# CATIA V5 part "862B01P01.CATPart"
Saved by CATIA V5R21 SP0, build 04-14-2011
Part number: 862B01P01
Bounding box of the stored display mesh (mm): x -25.75 to 25.25, y -25.549 to 25.54, z -6.5 to 6.5
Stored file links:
  C:\Users\ALI OZGUN\Desktop\alhan\862B01P01.CATPart
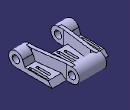
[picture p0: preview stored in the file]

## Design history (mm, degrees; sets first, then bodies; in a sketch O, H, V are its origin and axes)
Body1 (main body)
  Sketch1 on yz-plane, origin (0, 0, 0), H (0, 1, 0), V (0, 0, 1)
    construction line L1 (-19.05, 0) -> (19.05, 0)
    point P1 (-19.05, 0)
    point P2 (19.05, 0)
    line L2 (-19.05, 6.5) -> (19.05, 6.5)
    line L3 (19.05, -6.5) -> (-19.05, -6.5)
    arc A1 centre (19.05, 0) radius 6.5 from (19.05, 6.5) to (19.05, -6.5) cw
    arc A2 centre (-19.05, 0) radius 6.5 from (-19.05, -6.5) to (-19.05, 6.5) cw
    circle A3 centre (19.05, 0) radius 3.25
    circle A4 centre (-19.05, 0) radius 3.25
    distance L1 L2 = 6.5
    length L1 = 38.1
    distance P2 V = 19.05
    radius A3 = 3.25
    radius A4 = 3.25
    coincidence: P1 H
    horizontal: L1 H
    tangency: A1 L2, A2 L2, A1 L3, A2 L3
  Pad1: profile Sketch1, direction (1, 0, 0), length 76.5, mirrored extent
  Sketch2 on face of Pad1 from Sketch1.L2, origin (0, 0, 6.5), H (1, 0, 0), V (0, 1, 0)
    line L1 (38, -14) -> (64, -14)
    line L2 (64, -14) -> (64, -36.0786)
    line L3 (64, -36.0786) -> (38, -36.0786)
    line L4 (38, -36.0786) -> (38, -14)
    line L5 (-13, -14) -> (13, -14)
    line L6 (13, -14) -> (13, -36.0786)
    line L7 (13, -36.0786) -> (-13, -36.0786)
    line L8 (-13, -36.0786) -> (-13, -14)
    point P7 (13, -36.0786)
    line L9 (-64, -14) -> (-38, -14)
    line L10 (-38, -14) -> (-38, -32.269)
    line L11 (-38, -32.269) -> (-64, -32.269)
    line L12 (-64, -32.269) -> (-64, -14)
    line L13 (85.7823, 31.3847) -> (63.5, 31.3847)
    line L14 (63.5, 31.3847) -> (63.5, 14)
    line L15 (63.5, 14) -> (85.7823, 14)
    line L16 (85.7823, 14) -> (85.7823, 31.3847)
    point P17 (12.5, 31.3847)
    line L17 (12.5, 31.3847) -> (38.5, 31.3847)
    line L18 (38.5, 31.3847) -> (38.5, 14)
    line L19 (38.5, 14) -> (12.5, 14)
    line L20 (12.5, 14) -> (12.5, 31.3847)
    point P19 (38.5, 14)
    line L21 (-38.5, 32.0801) -> (-12.5, 32.0801)
    line L22 (-12.5, 32.0801) -> (-12.5, 14)
    line L23 (-12.5, 14) -> (-38.5, 14)
    line L24 (-38.5, 14) -> (-38.5, 32.0801)
    point P23 (-12.5, 14)
    line L25 (-81.4786, 33.8185) -> (-63.5, 33.8185)
    line L26 (-63.5, 33.8185) -> (-63.5, 14)
    line L27 (-63.5, 14) -> (-81.4786, 14)
    line L28 (-81.4786, 14) -> (-81.4786, 33.8185)
    point P27 (-63.5, 14)
    reference projected line E1 (76.5, 19.05) -> (76.5, -19.05) from edge [face of Pad1 from Sketch1.L2 | end face of Pad1]
    reference projected line E2 (-76.5, 19.05) -> (-76.5, -19.05) from edge [start face of Pad1 | face of Pad1 from Sketch1.L2]
    reference projected line E3 (-76.5, 19.05) -> (-76.5, -19.05) from edge [start face of Pad1 | face of Pad1 from Sketch1.L2]
    reference projected line E4 (76.5, 19.05) -> (76.5, -19.05) from edge [face of Pad1 from Sketch1.L2 | end face of Pad1]
    distance L14 E1 = 13
    distance L26 E2 = 13
    distance L12 E3 = 12.5
    distance L2 E4 = 12.5
    distance L23 L5 = 28
    distance L5 H = 14
    distance L4 L2 = 26
    distance L12 L10 = 26
    distance L10 L8 = 25
    distance L6 L4 = 25
    distance L24 L26 = 25
    distance L18 L14 = 25
    distance L26 L22 = 51
    distance L20 L18 = 26
    horizontal: L1 H, L3 H, L5 H, L7 H, L9 H, L11 H, L13 H, L15 H, L17 H, L19 H, L21 H, L23 H, L25 H, L27 H
    vertical: L2 V, L4 V, L6 V, L8 V, L10 V, L12 V, L14 V, L16 V, L18 V, L20 V, L22 V, L24 V, L26 V, L28 V
    coincidence: P7 L3, P17 L13, P19 L15, P23 L15, P27 L15, L1 L5, L9 L5
  Pocket1: profile Sketch2, direction (0, 0, -1), length 53.5
  Sketch3 on end face of Pad1, origin (76.5, 0, 0), H (0, 1, 0), V (0, 0, 1)
    projected arc E1 centre (19.05, 0) radius 6.5 from (19.05, -6.5) to (19.05, 6.5) ccw from edge [face of Pocket1 from Sketch2.L14 | face of Pad1 from Sketch1.A1]
    projected arc E2 centre (19.05, 0) radius 6.5 from (19.05, -6.5) to (13.0358, 2.4657) ccw from edge [face of Pocket1 from Sketch2.L14 | face of Pad1 from Sketch1.A1]
    point P1 (19.05, -6.5)
    projected arc E3 centre (-19.05, 0) radius 6.5 from (-19.05, 6.5) to (-19.05, -6.5) ccw from edge [face of Pad1 from Sketch1.A2 | end face of Pad1]
    projected arc E4 centre (-19.05, 0) radius 6.5 from (-13.0358, 2.4657) to (-19.05, -6.5) ccw from edge [face of Pad1 from Sketch1.A2 | end face of Pad1]
    point P4 (-19.05, -6.5)
    projected line E5 (-19.05, -6.5) -> (14, -6.5) from edge [face of Pad1 from Sketch1.L3 | end face of Pad1]
    point P5 (-19.05, -6.5)
    projected line E6 (19.05, -6.5) -> (14, -6.5) from edge [face of Pocket1 from Sketch2.L14 | face of Pad1 from Sketch1.L3]
    point P7 (19.05, -6.5)
    line L1 (-13.0358, 2.4657) -> (-11, -2.5)
    line L2 (-11, -2.5) -> (11, -2.5)
    point P10 (11, -2.5)
    line L3 (11, -2.5) -> (13.0358, 2.4657)
    distance L2 E5 = 4
    length L2 = 22
    distance P10 V = 11
    horizontal: L2 H
    tangency: L3 E1, L1 E3
    coincidence: P1 P7, P4 P5
  Pocket2: profile Sketch3, direction (-1, 0, 0), length 172.5, outer side
  Sketch4 on face of Pocket2 from Sketch3.L2, origin (0, 0, -2.5), H (1, 0, 0), V (0, 1, 0)
    projected line E1 (38, -14) -> (38, -25.55) from edge [face of Pocket2 | face of Pocket1 from Sketch2.L4]
    projected line E2 (38, -14) -> (38, -19.05) from edge [face of Pocket2 | face of Pocket1 from Sketch2.L4]
    point P1 (38, -14)
    point P2 (38, -25.55)
    projected line E3 (13, -25.55) -> (13, -14) from edge [face of Pocket2 | face of Pocket1 from Sketch2.L6]
    projected line E4 (13, -19.05) -> (13, -14) from edge [face of Pocket2 | face of Pocket1 from Sketch2.L6]
    point P3 (13, -25.55)
    point P4 (13, -14)
    projected line E5 (64, -25.55) -> (64, -14) from edge [face of Pocket2 | face of Pocket1 from Sketch2.L2]
    projected line E6 (64, -19.05) -> (64, -14) from edge [face of Pocket2 | face of Pocket1 from Sketch2.L2]
    point P5 (64, -25.55)
    point P6 (64, -14)
    projected line E7 (38.5, 14) -> (38.5, 25.55) from edge [face of Pocket2 | face of Pocket1 from Sketch2.L18]
    projected line E8 (38.5, 14) -> (38.5, 19.05) from edge [face of Pocket2 | face of Pocket1 from Sketch2.L18]
    point P7 (38.5, 14)
    point P8 (38.5, 25.55)
    projected line E9 (63.5, 14) -> (63.5, 25.55) from edge [face of Pocket1 from Sketch2.L14 | face of Pocket2]
    projected line E10 (63.5, 14) -> (63.5, 19.05) from edge [face of Pocket1 from Sketch2.L14 | face of Pocket2]
    point P9 (63.5, 14)
    point P10 (63.5, 25.55)
    projected line E11 (12.5, 25.55) -> (12.5, 14) from edge [face of Pocket2 | face of Pocket1 from Sketch2.L20]
    projected line E12 (12.5, 19.05) -> (12.5, 14) from edge [face of Pocket2 | face of Pocket1 from Sketch2.L20]
    point P11 (12.5, 25.55)
    point P12 (12.5, 14)
    offset line E13 (9.5, 25.55) -> (9.5, 14) from edge [face of Pocket2 | face of Pocket1 from Sketch2.L20]
    offset line E14 (9.5, 19.05) -> (9.5, 14) from edge [face of Pocket2 | face of Pocket1 from Sketch2.L20]
    point P13 (9.5, 25.55)
    point P14 (9.5, 14)
    offset line E15 (16, -25.55) -> (16, -14) from edge [face of Pocket2 | face of Pocket1 from Sketch2.L6]
    offset line E16 (16, -19.05) -> (16, -14) from edge [face of Pocket2 | face of Pocket1 from Sketch2.L6]
    point P15 (16, -25.55)
    point P16 (16, -14)
    offset line E17 (35, -14) -> (35, -25.55) from edge [face of Pocket2 | face of Pocket1 from Sketch2.L4]
    offset line E18 (35, -14) -> (35, -19.05) from edge [face of Pocket2 | face of Pocket1 from Sketch2.L4]
    point P17 (35, -14)
    point P18 (35, -25.55)
    offset line E19 (41.5, 14) -> (41.5, 25.55) from edge [face of Pocket2 | face of Pocket1 from Sketch2.L18]
    offset line E20 (41.5, 14) -> (41.5, 19.05) from edge [face of Pocket2 | face of Pocket1 from Sketch2.L18]
    point P19 (41.5, 14)
    point P20 (41.5, 25.55)
    offset line E21 (60.5, 14) -> (60.5, 25.55) from edge [face of Pocket1 from Sketch2.L14 | face of Pocket2]
    offset line E22 (60.5, 14) -> (60.5, 19.05) from edge [face of Pocket1 from Sketch2.L14 | face of Pocket2]
    point P21 (60.5, 14)
    point P22 (60.5, 25.55)
    offset line E23 (67, -25.55) -> (67, -14) from edge [face of Pocket2 | face of Pocket1 from Sketch2.L2]
    offset line E24 (67, -19.05) -> (67, -14) from edge [face of Pocket2 | face of Pocket1 from Sketch2.L2]
    point P23 (67, -25.55)
    point P24 (67, -14)
    line L1 (13, -14) -> (9.5, 14)
    line L2 (16, -14) -> (12.5, 14)
    line L3 (35, -14) -> (38.5, 14)
    line L4 (38, -14) -> (41.5, 14)
    line L5 (64, -14) -> (60.5, 14)
    line L6 (67, -14) -> (63.5, 14)
    projected line E25 through (0, -19.05) direction (1, 0) from axis of face of Pocket2
    projected line E26 (13, -19.05) -> (16, -19.05) from axis of face of Pocket2
    projected line E27 (64, -19.05) -> (67, -19.05) from axis of face of Pocket2
    projected line E28 (35, -19.05) -> (38, -19.05) from axis of face of Pocket2
    point P25 (-10000000, -19.05)
    point P26 (10000000, -19.05)
    point P27 (67, -19.05)
    point P28 (38, -19.05)
    point P29 (64, -19.05)
    point P30 (64, -19.05)
    point P31 (38, -19.05)
    point P32 (35, -19.05)
    point P33 (16, -19.05)
    point P34 (35, -19.05)
    point P35 (16, -19.05)
    point P36 (13, -19.05)
    point P37 (13, -19.05)
    projected line E29 through (0, 19.05) direction (1, 0) from axis of face of Pocket2
    projected line E30 (9.5, 19.05) -> (12.5, 19.05) from axis of face of Pocket2
    projected line E31 (38.5, 19.05) -> (41.5, 19.05) from axis of face of Pocket2
    projected line E32 (60.5, 19.05) -> (63.5, 19.05) from axis of face of Pocket2
    point P38 (-10000000, 19.05)
    point P39 (10000000, 19.05)
    point P40 (63.5, 19.05)
    point P41 (9.5, 19.05)
    point P42 (9.5, 19.05)
    point P43 (12.5, 19.05)
    point P44 (12.5, 19.05)
    point P45 (38.5, 19.05)
    point P46 (38.5, 19.05)
    point P47 (41.5, 19.05)
    point P48 (60.5, 19.05)
    point P49 (41.5, 19.05)
    point P50 (60.5, 19.05)
    point P51 (-10000000, -19.05)
    point P52 (10000000, -19.05)
    point P53 (-10000000, 19.05)
    point P54 (10000000, 19.05)
    construction line L7 through (0, -19.05) direction (-1, 0)
    construction line L8 through (0, 19.05) direction (-1, 0)
    point P55 (-10000000, -19.05)
    point P56 (10000000, -19.05)
    point P57 (-16, -19.05)
    point P58 (-13, -19.05)
    point P59 (-67, -19.05)
    point P60 (-64, -19.05)
    point P61 (-38, -19.05)
    point P62 (-35, -19.05)
    point P63 (-38, -25.55)
    point P64 (-38, -14)
    point P65 (-38, -19.05)
    point P66 (-13, -14)
    point P67 (-13, -25.55)
    point P68 (-13, -19.05)
    point P69 (-64, -14)
    point P70 (-64, -25.55)
    point P71 (-64, -19.05)
    point P72 (-38.5, 25.55)
    point P73 (-38.5, 14)
    point P74 (-38.5, 19.05)
    point P75 (-63.5, 25.55)
    point P76 (-63.5, 14)
    point P77 (-63.5, 19.05)
    point P78 (-12.5, 14)
    point P79 (-12.5, 25.55)
    point P80 (-12.5, 19.05)
    point P81 (-9.5, 14)
    point P82 (-9.5, 25.55)
    point P83 (-9.5, 19.05)
    point P84 (-16, -14)
    point P85 (-16, -25.55)
    point P86 (-16, -19.05)
    point P87 (-35, -25.55)
    point P88 (-35, -14)
    point P89 (-35, -19.05)
    point P90 (-41.5, 25.55)
    point P91 (-41.5, 14)
    point P92 (-41.5, 19.05)
    point P93 (-60.5, 25.55)
    point P94 (-60.5, 14)
    point P95 (-60.5, 19.05)
    point P96 (-67, -14)
    point P97 (-67, -25.55)
    line L9 (-13, -14) -> (-9.5, 14)
    line L10 (-16, -14) -> (-12.5, 14)
    line L11 (-35, -14) -> (-38.5, 14)
    line L12 (-38, -14) -> (-41.5, 14)
    line L13 (-64, -14) -> (-60.5, 14)
    line L14 (-67, -14) -> (-63.5, 14)
    point P98 (-10000000, 19.05)
    point P99 (10000000, 19.05)
    point P100 (-12.5, 19.05)
    point P101 (-9.5, 19.05)
    point P102 (-41.5, 19.05)
    point P103 (-38.5, 19.05)
    point P104 (-60.5, 19.05)
    construction line L15 through (0, -19.05) direction (-1, 0)
    line L16 (-13, -19.05) -> (-16, -19.05)
    line L17 (-64, -19.05) -> (-67, -19.05)
    line L18 (-35, -19.05) -> (-38, -19.05)
    construction line L19 (-38, -14) -> (-38, -25.55)
    line L20 (-38, -14) -> (-38, -19.05)
    construction line L21 (-13, -25.55) -> (-13, -14)
    line L22 (-13, -19.05) -> (-13, -14)
    construction line L23 (-64, -25.55) -> (-64, -14)
    line L24 (-64, -19.05) -> (-64, -14)
    construction line L25 (-38.5, 14) -> (-38.5, 25.55)
    line L26 (-38.5, 14) -> (-38.5, 19.05)
    construction line L27 (-63.5, 14) -> (-63.5, 25.55)
    line L28 (-63.5, 14) -> (-63.5, 19.05)
    construction line L29 (-12.5, 25.55) -> (-12.5, 14)
    line L30 (-12.5, 19.05) -> (-12.5, 14)
    construction line L31 (-9.5, 25.55) -> (-9.5, 14)
    line L32 (-9.5, 19.05) -> (-9.5, 14)
    construction line L33 (-16, -25.55) -> (-16, -14)
    line L34 (-16, -19.05) -> (-16, -14)
    construction line L35 (-35, -14) -> (-35, -25.55)
    line L36 (-35, -14) -> (-35, -19.05)
    construction line L37 (-41.5, 14) -> (-41.5, 25.55)
    line L38 (-41.5, 14) -> (-41.5, 19.05)
    construction line L39 (-60.5, 14) -> (-60.5, 25.55)
    line L40 (-60.5, 14) -> (-60.5, 19.05)
    construction line L41 (-67, -25.55) -> (-67, -14)
    line L42 (-67, -19.05) -> (-67, -14)
    construction line L43 through (0, 19.05) direction (-1, 0)
    line L44 (-9.5, 19.05) -> (-12.5, 19.05)
    line L45 (-38.5, 19.05) -> (-41.5, 19.05)
    line L46 (-60.5, 19.05) -> (-63.5, 19.05)
    parallelism: L2 L1, L4 L3
    coincidence: E1 P28, E5 P29, E25 P30, E25 P31, E25 P32, E15 P33, E17 P34, E25 P35, E25 P36, E3 P37, E13 P41, E29 P42, E29 P43, E11 P44, E7 P45, E29 P46, E29 P47, E29 P48, E19 P49, E21 P50, P28 P31, P29 P30, P32 P34, P33 P35, P36 P37, P41 P42, P43 P44, P45 P46, P47 P49, P48 P50
    symmetry: P26 P51 V, P25 P52 V, E25 L7 V, P39 P53 V, P38 P54 V, E29 L8 V, P26 P55 V, P25 P56 V, P33 P57 V, P37 P58 V, P27 P59 V, P29 P60 V, P28 P61 V, P34 P62 V, E25 L15 V, P2 P63 V, P1 P64 V, P31 P65 V, E1 L19 V, P4 P66 V, P3 P67 V, P36 P68 V, E3 L21 V, P6 P69 V, P5 P70 V, P30 P71 V, E5 L23 V, P8 P72 V, P7 P73 V, P46 P74 V, E7 L25 V, P10 P75 V, P9 P76 V, P40 P77 V, E9 L27 V, P12 P78 V, P11 P79 V, P43 P80 V, E11 L29 V, P14 P81 V, P13 P82 V, P42 P83 V, E13 L31 V, P16 P84 V, P15 P85 V, P35 P86 V, E15 L33 V, P18 P87 V, P17 P88 V, P32 P89 V, E17 L35 V, P20 P90 V, P19 P91 V, P47 P92 V, E19 L37 V, P22 P93 V, P21 P94 V, P48 P95 V, E21 L39 V, P24 P96 V, P23 P97 V, E23 L41 V, L1 L9 V, L2 L10 V, L3 L11 V, L4 L12 V, L5 L13 V, L6 L14 V, P39 P98 V, P38 P99 V, P44 P100 V, P41 P101 V, P49 P102 V, P45 P103 V, P50 P104 V, E29 L43 V, E25 L18 V, E25 L17 V, E25 L16 V, E1 L20 V, E3 L22 V, E5 L24 V, E7 L26 V, E9 L28 V, E11 L30 V, E13 L32 V, E15 L34 V, E17 L36 V, E19 L38 V, E21 L40 V, E23 L42 V, E29 L46 V, E29 L45 V, E29 L44 V
  Pad2: profile Sketch4, direction (0, 0, 1), length 9
  Sketch5 on yz-plane, origin (0, 0, 0), H (0, 1, 0), V (0, 0, 1)
    projected circle E1 centre (-19.05, 0) radius 3.25 from edge [end face of Pad1 | face of Pad1 from Sketch1.A4]
    circle A1 centre (19.05, 0) radius 3.25
    reference projected circle E2 centre (19.05, 0) radius 3.25 from edge [face of Pad1 from Sketch1.A3 | face of Pad2]
    coincidence: A1 E2
  Pocket3: profile Sketch5, direction (-1, 0, 0), length 95, mirrored extent
  RemoveFace1: RemoveFaces (face of Pocket2 from Sketch3.L3; face of Pocket2; face of Pocket2 from Sketch3.L3; face of Pocket2; face of Pocket2 from Sketch3.L1; face of Pocket2; face of Pocket2 from Sketch3.L1; face of Pocket2; face of Pocket2; face of Pocket2; face of Pocket2; face of Pocket2 from Sketch3.L3; face of Pocket2 from Sketch3.L3; face of Pocket2 from Sketch3.L1)
  Chamfer1: length 4, angle 45, on edge [face of Pocket1 from Sketch2.L27 | face of Pocket2 from Sketch3.L2]; edge [face of Pocket1 from Sketch2.L9 | face of Pocket2 from Sketch3.L2]; edge [face of Pocket1 from Sketch2.L19 | face of Pocket2 from Sketch3.L2]; edge [face of Pocket1 from Sketch2.L5 | face of Pocket2 from Sketch3.L2]; edge [face of Pocket1 from Sketch2.L1 | face of Pocket2 from Sketch3.L2]; edge [face of Pocket1 from Sketch2.L15 | face of Pocket2 from Sketch3.L2]; edge [face of Pocket1 from Sketch2.L23 | face of Pocket2 from Sketch3.L2]
  Sketch6 on face of Pocket2, origin (0, 0, -6.5), H (1, 0, 0), V (0, -1, 0)
    line L1 (-25.75, 44.4621) -> (25.25, 44.4621)
    line L2 (25.25, 44.4621) -> (25.25, -35.3991)
    line L3 (25.25, -35.3991) -> (-25.75, -35.3991)
    line L4 (-25.75, -35.3991) -> (-25.75, 44.4621)
    distance L4 L2 = 51
    distance L4 V = 25.75
    horizontal: L1 H, L3 H
    vertical: L2 V, L4 V
  Pocket4: profile Sketch6, direction (0, 0, 1), length 25, mirrored extent, outer side
  Body2
    Solid1: solid without history
  Remove1: tool Body2
Body3
  Solid2: linked copy from another document
  Translate1: Direction zx-plane, Length 38.1, ToTransfor Solid2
